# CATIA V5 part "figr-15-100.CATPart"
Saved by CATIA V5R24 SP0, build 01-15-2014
Part number: Part1
Bounding box of the stored display mesh (mm): x -52.43 to 60.529, y -25.631 to 32.893, z 0 to 4
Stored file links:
  D:\KAVITA\CATIA V5-6R2014 Project_ Kavita\CATIA V5-6R2014_partfiles\Partfiles\c15_catia_v5-6r2014_prt\figr-15-100.CATPart
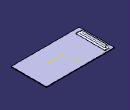
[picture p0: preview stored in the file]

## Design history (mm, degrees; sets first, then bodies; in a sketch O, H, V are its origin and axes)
SheetMetalParameters1: Thickness 1, BendRadius 5, KFactor 0.5 {= log(min(100,max(20*SheetMetalParameters1.BendRadius,SheetMetalParameters1.Thickness)/SheetMetalParameters1.Thickness))/log(100)/2}, ReliefRadialLength 1, ReliefAxialLength 2, MinimumBendRadius 0
Body1 (main body)
  Sketch1 on xy-plane, origin (0, 0, 0), H (1, 0, 0), V (0, 1, 0)
    line L1 (-52.4297, 32.8934) -> (60.5286, 32.8934)
    line L2 (60.5286, 32.8934) -> (60.5286, -25.6312)
    line L3 (60.5286, -25.6312) -> (-52.4297, -25.6312)
    line L4 (-52.4297, -25.6312) -> (-52.4297, 32.8934)
    horizontal: L1 H, L3 H
    vertical: L2 V, L4 V
  Wall1: Thickness 1, Profile Sketch1
  Sketch2 on face of Wall1, origin (0, 0, 1), H (1, 0, 0), V (0, 1, 0)
    line L1 (-47.3159, -16.5837) -> (-43.073, -16.5837)
    line L2 (-43.073, -16.5837) -> (-43.073, 26.788)
    line L3 (-43.073, 26.788) -> (-47.3159, 26.788)
    line L4 (-47.3159, 26.788) -> (-47.3159, -16.5837)
    horizontal: L1 H, L3 H
    vertical: L2 V, L4 V
  d_Stamp1: Stamp_FilletRadius 2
